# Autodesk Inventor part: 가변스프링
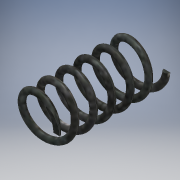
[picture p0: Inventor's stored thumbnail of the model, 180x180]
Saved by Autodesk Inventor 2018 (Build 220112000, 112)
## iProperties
Created: 2020-02
Part Number: 가변스프링
Material: 강철
Document SubType Name: Modeling
Designer: Administrator
Mass: 6.43013 g
Surface Area: 16.6219 cm^2
Volume: 0.819124 cm^3
Density: 7.85 g/cm^3
Appearance: 플레이트
Author: Administrator
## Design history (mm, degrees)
sketch "스케치1"
  geometry: L1 (0, 0)-(7, 0); L2 (7, 0)-(7, 35.5); L3 (7, 35.5)-(0, 35.5); L4 (0, 35.5)-(0, 0); C1 r 1 at (7, 0)
  constraints: 8 end point, 2 parallel, 1 centre point, 1 coincident, 1 horizontal, 1 perpendicular
  dimensions: "d0" = 14 diameter of L1.end L4; "d1" = 35.5 distance of L3.end L1.start (derived); "d2" = 2 diameter of C1
feature "코일1" sketch "스케치1" pitch "d3" = 10; turns "d5" = 6; dims "d4" = 35.5 (= d1), "d6" = 0, angle "d7" = 90 deg, angle "d8" = 90 deg, "d9" = 0, "d10" = 0
sketch "스케치2"
  geometry: L1 (-6, 0)-(-8, 0) reference; 1 further point
  constraints: 1 horizontal alignment
extrude "돌출1" cut sketch "스케치2" extent not by distance; stored distance "d11" = 10; taper "d12" = 0 deg
node "작업 평면1"
sketch "스케치3"
  geometry: L1 (-1, 0)-(1, 0) reference; 1 further point
  constraints: 1 horizontal alignment
extrude "돌출2" cut sketch "스케치3" extent not by distance; stored distance "d14" = 10; taper "d15" = 0 deg
node "솔리드1"
node "절단 모서리 투영1"
node "절단 모서리 투영2"
other parameters: "d13" = 90 deg
